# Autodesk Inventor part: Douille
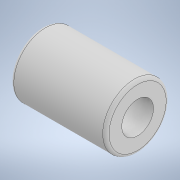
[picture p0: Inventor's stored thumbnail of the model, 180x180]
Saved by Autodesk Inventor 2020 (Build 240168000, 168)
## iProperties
Created: 2023-10
Part Number: Douille
Material: Générique
Document SubType Name: Modeling
Designer: bruno
Density: 1 g/cm^3
Appearance: Par défaut
Author: bruno
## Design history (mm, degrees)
sketch "Esquisse1"
  geometry: C1 r 5 at (0, 0); C2 r 2.5 at (0, 0); 1 further point
  constraints: 2 centre point, 2 coincident
  dimensions: "d0" = 10 diameter of C1; "d1" = 5 diameter of C2
extrude "Extrusion1" new body sketch "Esquisse1" distance "d2" = 15; taper "d3" = 0 deg
fillet "Congé1" dims "d4" = 0.5
node "Solide1"
